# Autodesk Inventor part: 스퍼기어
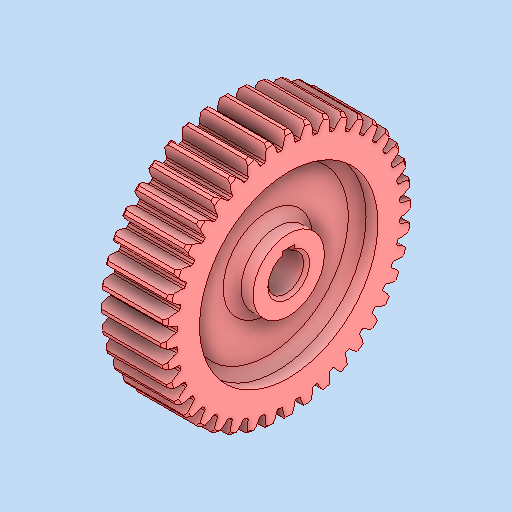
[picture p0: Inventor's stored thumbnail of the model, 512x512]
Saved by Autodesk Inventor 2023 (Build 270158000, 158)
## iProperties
Created: 2024-11
Part Number: 스퍼기어
Material: 강철, 탄소
Document SubType Name: Modeling
Designer: asung
Density: 7.85 g/cm^3
Appearance: 기본값
Author: jhkim
Sending System: Autodesk Inventor 2025
Preprocessor: ST-DEVELOPER v20
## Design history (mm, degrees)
feature "솔리드1"
node "솔리드2"
